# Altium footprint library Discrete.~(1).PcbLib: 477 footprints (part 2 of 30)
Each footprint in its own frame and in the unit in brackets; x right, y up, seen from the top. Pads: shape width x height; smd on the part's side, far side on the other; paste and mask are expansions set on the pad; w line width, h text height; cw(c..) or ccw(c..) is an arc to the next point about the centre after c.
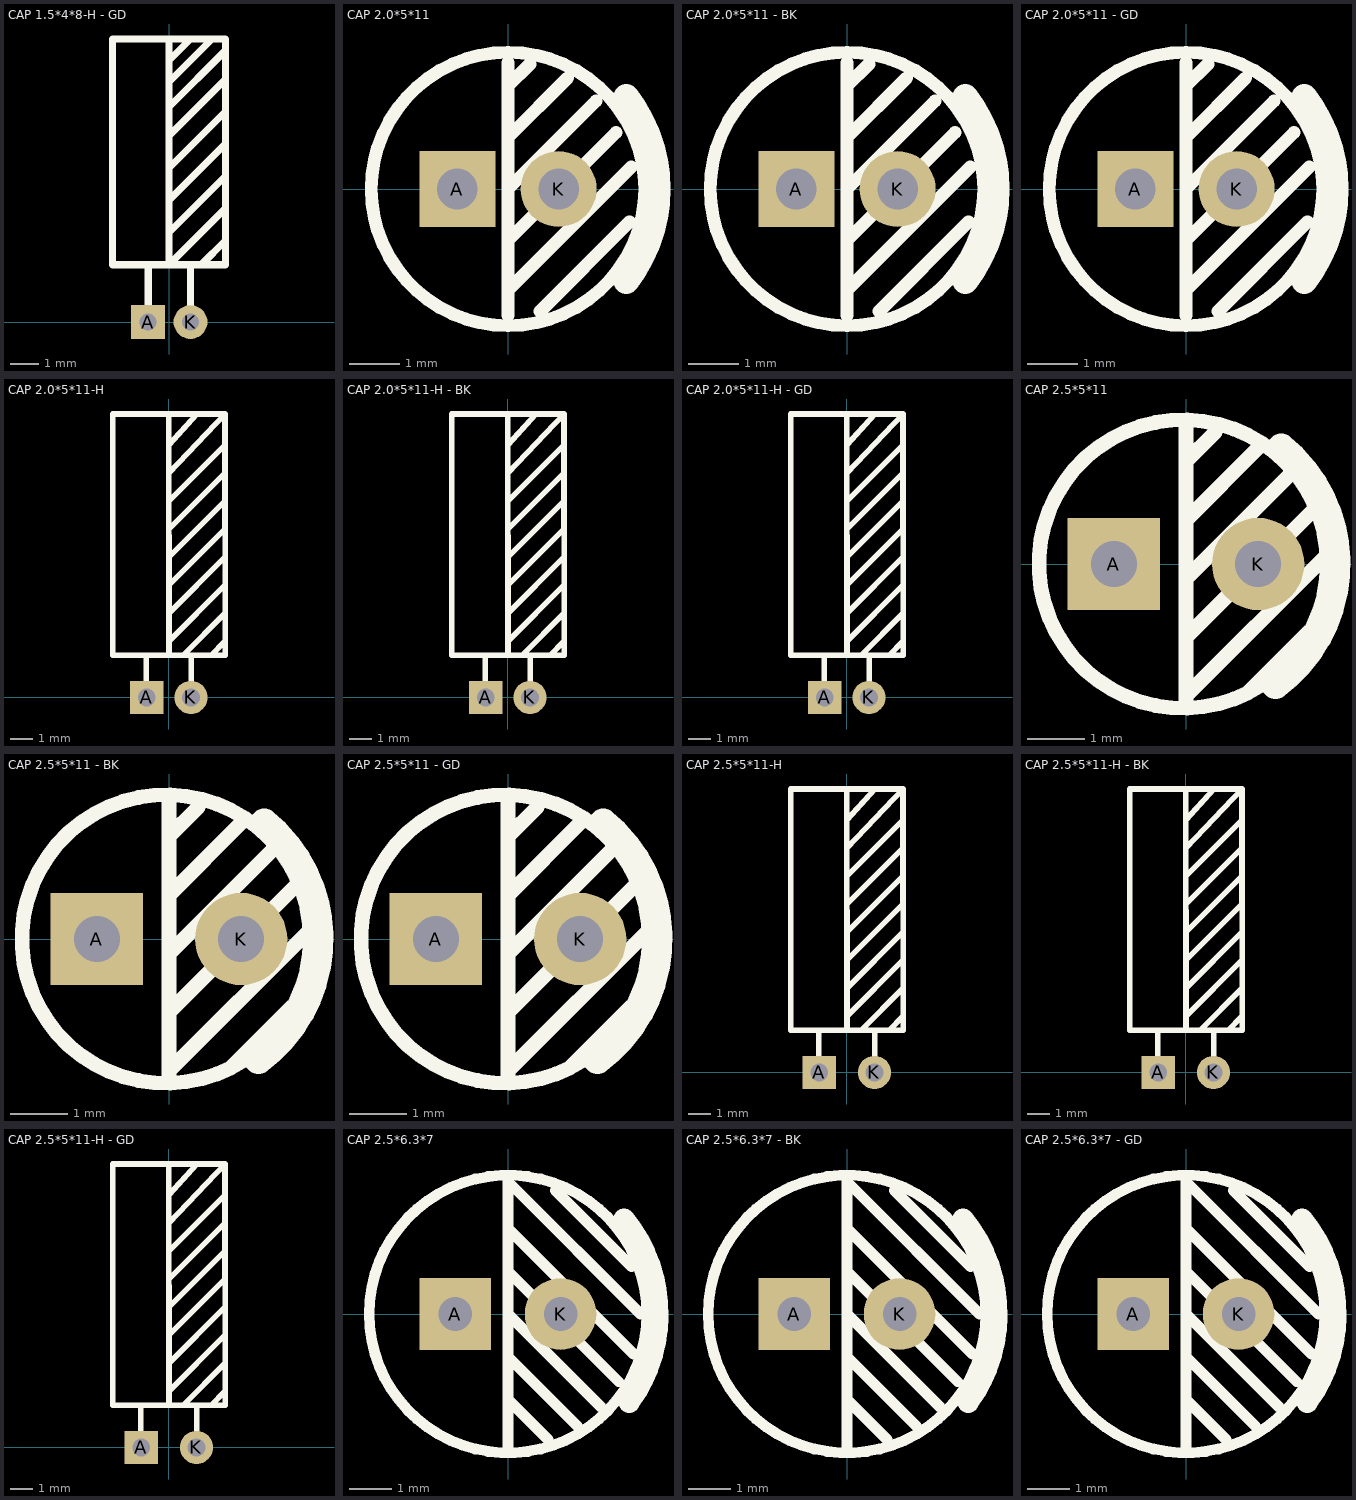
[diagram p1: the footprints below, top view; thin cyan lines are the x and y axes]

## CAP 1.5*4*8-H - GD [mm] "脚距1.5mm直径4mm高度8mm"
pads (2):
  rect 1.2x1.2 hole 0.6: A(-0.75,0)
  round 1.2 hole 0.6: K(0.75,0)
Top Overlay:
  lines w0.254: -0.75,0 -0.75,2 ; -0.012,3.175 1.988,5.175 1.988,5.207 ; -0.012,4.318 1.988,6.318 1.988,6.35 ; -0.012,5.461 1.988,7.461 1.988,7.493 ; -0.012,6.604 1.988,8.604 1.988,8.636 ; -0.012,7.62 1.965,9.597 ccw(c1.911,9.652) 1.988,9.652 ; -0.012,8.509 1.51,10.031 cw(c1.512,10.03) 1.512,10.032 ; -0.012,9.271 0.748,10.031 cw(c0.75,10.03) 0.75,10.032 ; -0.012,10.032 -0.012,2.032 ; 0.75,0 0.75,2 ; 0.877,2.921 -0.012,2.032 ; 1.131,2.032 1.988,2.889 1.988,2.921 ; 1.988,4.064 1.988,4.032 -0.012,2.032 ; -2.012,2.032 1.988,2.032 1.988,10.032 -2.012,10.032 -2.012,2.032
3D body "CAP 1.5X4X8-H.STEP": height 4.02, standoff -3.48, extent -2,-0.25 2.02,10

## CAP 2.0*5*11 [mm] "脚距2mm直径5mm高度11mm"
pads (2):
  rect 1.5x1.5 hole 0.8: A(-1,0)
  round 1.5 hole 0.8: K(1,0)
Top Overlay:
  circle w0.254: c0,0 r2.7
  lines w0.254: 0,-2.5 0,-2 ; 0,-1.016 2.134,1.118 ; 0,0 1.74,1.74 ; 0,1.016 1.181,2.197 ; 0,2.032 0.432,2.464 ; 0,2.5 0,-2 ; 0.635,-2.413 2.4,-0.648 ; 2.435,0.435 0,-2
  lines w0.5: 2.338,-1.819 ccw(c0,0) 2.338,1.819
3D body "CAP 2X5X11.STEP": height 11.04, standoff -3.42, extent -2.5,-2.499 2.51,2.499

## CAP 2.0*5*11 - BK [mm] "脚距2mm直径5mm高度11mm"
pads (2):
  rect 1.5x1.5 hole 0.8: A(-1,0)
  round 1.5 hole 0.8: K(1,0)
Top Overlay:
  circle w0.254: c0,0 r2.7
  lines w0.254: 0,-2.5 0,-2 ; 0,-1.016 2.134,1.118 ; 0,0 1.74,1.74 ; 0,1.016 1.181,2.197 ; 0,2.032 0.432,2.464 ; 0,2.5 0,-2 ; 0.635,-2.413 2.4,-0.648 ; 2.435,0.435 0,-2
  lines w0.5: 2.338,-1.819 ccw(c0,0) 2.338,1.819
3D body "CAP 2X5X11.STEP": height 11.04, standoff -3.42, extent -2.5,-2.499 2.51,2.499

## CAP 2.0*5*11 - GD [mm] "脚距2mm直径5mm高度11mm"
pads (2):
  rect 1.5x1.5 hole 0.8: A(-1,0)
  round 1.5 hole 0.8: K(1,0)
Top Overlay:
  circle w0.254: c0,0 r2.7
  lines w0.254: 0,-2.5 0,-2 ; 0,-1.016 2.134,1.118 ; 0,0 1.74,1.74 ; 0,1.016 1.181,2.197 ; 0,2.032 0.432,2.464 ; 0,2.5 0,-2 ; 0.635,-2.413 2.4,-0.648 ; 2.435,0.435 0,-2
  lines w0.5: 2.338,-1.819 ccw(c0,0) 2.338,1.819
3D body "CAP 2X5X11.STEP": height 11.04, standoff -3.42, extent -2.5,-2.499 2.51,2.499

## CAP 2.0*5*11-H [mm] "脚距2mm直径5mm高度11mm"
pads (2):
  rect 1.5x1.5 hole 0.8: A(-1,0)
  round 1.5 hole 0.8: K(1,0)
Top Overlay:
  lines w0.254: -1.016,0.762 -1.016,1.905 ; 0,2.54 2.548,5.08 ; 0,6.35 2.54,8.89 ; 0.001,11.43 1.27,12.827 ; 0,12.827 0.006,1.905 ; 0.001,10.16 2.54,12.827 ; 0.003,7.62 2.543,10.16 ; 0.002,8.89 2.541,11.43 ; 0.004,5.08 2.545,7.62 ; 0.005,3.81 2.547,6.35 ; 0.635,1.905 2.54,3.81 ; 1.016,0.762 1.016,1.905 ; 1.905,1.905 2.54,2.54 ; 2.54,12.827 2.552,1.905 -2.54,1.905 -2.54,12.827 2.54,12.827
3D body "CAP 2X5X11-H.STEP": height 5.02, standoff -3.48, extent -2.5,-0.25 2.51,12.96

## CAP 2.0*5*11-H - BK [mm] "脚距2mm直径5mm高度11mm"
pads (2):
  rect 1.5x1.5 hole 0.8: A(-1,0)
  round 1.5 hole 0.8: K(1,0)
Top Overlay:
  lines w0.254: -1.016,0.762 -1.016,1.905 ; 0,2.54 2.548,5.08 ; 0,6.35 2.54,8.89 ; 0.001,11.43 1.27,12.827 ; 0,12.827 0.006,1.905 ; 0.001,10.16 2.54,12.827 ; 0.003,7.62 2.543,10.16 ; 0.002,8.89 2.541,11.43 ; 0.004,5.08 2.545,7.62 ; 0.005,3.81 2.547,6.35 ; 0.635,1.905 2.54,3.81 ; 1.016,0.762 1.016,1.905 ; 1.905,1.905 2.54,2.54 ; 2.54,12.827 2.552,1.905 -2.54,1.905 -2.54,12.827 2.54,12.827
3D body "CAP 2X5X11-H.STEP": height 5.02, standoff -3.48, extent -2.5,-0.25 2.51,12.96

## CAP 2.0*5*11-H - GD [mm] "脚距2mm直径5mm高度11mm"
pads (2):
  rect 1.5x1.5 hole 0.8: A(-1,0)
  round 1.5 hole 0.8: K(1,0)
Top Overlay:
  lines w0.254: -1.016,0.762 -1.016,1.905 ; 0,2.54 2.548,5.08 ; 0,6.35 2.54,8.89 ; 0.001,11.43 1.27,12.827 ; 0,12.827 0.006,1.905 ; 0.001,10.16 2.54,12.827 ; 0.003,7.62 2.543,10.16 ; 0.002,8.89 2.541,11.43 ; 0.004,5.08 2.545,7.62 ; 0.005,3.81 2.547,6.35 ; 0.635,1.905 2.54,3.81 ; 1.016,0.762 1.016,1.905 ; 1.905,1.905 2.54,2.54 ; 2.54,12.827 2.552,1.905 -2.54,1.905 -2.54,12.827 2.54,12.827
3D body "CAP 2X5X11-H.STEP": height 5.02, standoff -3.48, extent -2.5,-0.25 2.51,12.96

## CAP 2.5*5*11 [mm] "脚距2.5mm直径5mm高度11mm"
pads (2):
  rect 1.6x1.6 hole 0.8: A(-1.25,0)
  round 1.6 hole 0.8: K(1.25,0)
Top Overlay:
  circle w0.254: c-0.05,0 r2.5
  lines w0.254: 0,-2.489 0,2.413 ; 0,-2.286 2.438,0.152 ; 0,-1.27 2.222,0.953 ; 0,-0.254 1.841,1.587 ; 0,0.762 1.27,2.032 ; 0,1.778 0.508,2.286 ; 1.079,-2.222 2.134,-1.168
  lines w0.5: 1.552,-2.086 ccw(c0,0) 1.651,2.008
3D body "CAP 2.5X5X11.STEP": height 11.03, standoff -3.43, extent -2.5,-2.499 2.51,2.499

## CAP 2.5*5*11 - BK [mm] "脚距2.5mm直径5mm高度11mm"
pads (2):
  rect 1.6x1.6 hole 0.8: A(-1.25,0)
  round 1.6 hole 0.8: K(1.25,0)
Top Overlay:
  circle w0.254: c-0.05,0 r2.5
  lines w0.254: 0,-2.489 0,2.413 ; 0,-2.286 2.438,0.152 ; 0,-1.27 2.222,0.953 ; 0,-0.254 1.841,1.587 ; 0,0.762 1.27,2.032 ; 0,1.778 0.508,2.286 ; 1.079,-2.222 2.134,-1.168
  lines w0.5: 1.552,-2.086 ccw(c0,0) 1.651,2.008
3D body "CAP 2.5X5X11.STEP": height 11.04, standoff -3.42, extent -2.5,-2.499 2.51,2.499

## CAP 2.5*5*11 - GD [mm] "脚距2.5mm直径5mm高度11mm"
pads (2):
  rect 1.6x1.6 hole 0.8: A(-1.25,0)
  round 1.6 hole 0.8: K(1.25,0)
Top Overlay:
  circle w0.254: c-0.05,0 r2.5
  lines w0.254: 0,-2.489 0,2.413 ; 0,-2.286 2.438,0.152 ; 0,-1.27 2.222,0.953 ; 0,-0.254 1.841,1.587 ; 0,0.762 1.27,2.032 ; 0,1.778 0.508,2.286 ; 1.079,-2.222 2.134,-1.168
  lines w0.5: 1.552,-2.086 ccw(c0,0) 1.651,2.008
3D body "CAP 2.5X5X11.STEP": height 11.04, standoff -3.42, extent -2.5,-2.537 2.51,2.461

## CAP 2.5*5*11-H [mm] "脚距2.5mm直径5mm高度11mm"
pads (2):
  rect 1.5x1.5 hole 0.8: A(-1.25,0)
  round 1.5 hole 0.8: K(1.25,0)
Top Overlay:
  lines w0.254: -1.266,0.762 -1.266,1.905 ; 0,2.54 2.548,5.08 ; 0,6.35 2.54,8.89 ; 0.001,11.43 1.27,12.827 ; 0,12.827 0.006,1.905 ; 0.001,10.16 2.54,12.827 ; 0.003,7.62 2.543,10.16 ; 0.002,8.89 2.541,11.43 ; 0.004,5.08 2.545,7.62 ; 0.005,3.81 2.547,6.35 ; 0.635,1.905 2.54,3.81 ; 1.266,0.762 1.266,1.905 ; 1.905,1.905 2.54,2.54 ; 2.54,12.827 -2.54,12.827 -2.54,1.905 2.552,1.905 2.54,12.827
3D body "CAP 2.5X5X11-H.STEP": height 5.02, standoff -3.48, extent -2.5,-0.25 2.51,12.96

## CAP 2.5*5*11-H - BK [mm] "脚距2.5mm直径5mm高度11mm"
pads (2):
  rect 1.5x1.5 hole 0.8: A(-1.25,0)
  round 1.5 hole 0.8: K(1.25,0)
Top Overlay:
  lines w0.254: -1.266,0.762 -1.266,1.905 ; 0,2.54 2.548,5.08 ; 0,6.35 2.54,8.89 ; 0.001,11.43 1.27,12.827 ; 0,12.827 0.006,1.905 ; 0.001,10.16 2.54,12.827 ; 0.003,7.62 2.543,10.16 ; 0.002,8.89 2.541,11.43 ; 0.004,5.08 2.545,7.62 ; 0.005,3.81 2.547,6.35 ; 0.635,1.905 2.54,3.81 ; 1.266,0.762 1.266,1.905 ; 1.905,1.905 2.54,2.54 ; 2.54,12.827 2.552,1.905 -2.54,1.905 -2.54,12.827 2.54,12.827
3D body "CAP 2.5X5X11-H.STEP": height 5.02, standoff -3.48, extent -2.5,-0.25 2.51,12.96

## CAP 2.5*5*11-H - GD [mm] "脚距2.5mm直径5mm高度11mm"
pads (2):
  rect 1.5x1.5 hole 0.8: A(-1.25,0)
  round 1.5 hole 0.8: K(1.25,0)
Top Overlay:
  lines w0.254: -1.266,0.762 -1.266,1.905 ; 0,2.54 2.548,5.08 ; 0,6.35 2.54,8.89 ; 0.001,11.43 1.27,12.827 ; 0,12.827 0.006,1.905 ; 0.001,10.16 2.54,12.827 ; 0.003,7.62 2.543,10.16 ; 0.002,8.89 2.541,11.43 ; 0.004,5.08 2.545,7.62 ; 0.005,3.81 2.547,6.35 ; 0.635,1.905 2.54,3.81 ; 1.266,0.762 1.266,1.905 ; 1.905,1.905 2.54,2.54 ; 2.54,12.827 2.552,1.905 -2.54,1.905 -2.54,12.827 2.54,12.827
3D body "CAP 2.5X5X11-H.STEP": height 5.02, standoff -3.48, extent -2.5,-0.25 2.51,12.96

## CAP 2.5*6.3*7 [mm] "脚距2.5mm直径6.3mm高度7mm"
pads (2):
  rect 1.7x1.7 hole 0.8: A(-1.25,0)
  round 1.7 hole 0.8: K(1.25,0)
Top Overlay:
  circle w0.254: c0,0 r3.3
  lines w0.254: 0,-3.15 0,3.15 ; 0,-2.032 0.953,-2.984 ; 0,-1.016 1.638,-2.654 ; 0,0 2.21,-2.21 ; 0,1.016 2.629,-1.613 ; 0,2.032 2.984,-0.953 ; 0,3.048 0.102,3.048 3.15,0 ; 1.13,2.934 2.934,1.13
  lines w0.504: 2.759,2.258 cw(c0,0) 2.883,-2.097
3D body "CAP 2.5X6.3X7.STEP": height 7.03, standoff -3.38, extent -3.15,-3.15 3.16,3.15

## CAP 2.5*6.3*7 - BK [mm] "脚距2.5mm直径6.3mm高度7mm"
pads (2):
  rect 1.7x1.7 hole 0.8: A(-1.25,0)
  round 1.7 hole 0.8: K(1.25,0)
Top Overlay:
  circle w0.254: c0,0 r3.3
  lines w0.254: 0,-3.15 0,3.15 ; 0,-2.032 0.953,-2.984 ; 0,-1.016 1.638,-2.654 ; 0,0 2.21,-2.21 ; 0,1.016 2.629,-1.613 ; 0,2.032 2.984,-0.953 ; 0,3.048 0.102,3.048 3.15,0 ; 1.13,2.934 2.934,1.13
  lines w0.504: 2.759,2.258 cw(c0,0) 2.883,-2.097
3D body "CAP 2.5X6.3X7.STEP": height 7.04, standoff -3.37, extent -3.15,-3.15 3.16,3.15

## CAP 2.5*6.3*7 - GD [mm] "脚距2.5mm直径6.3mm高度7mm"
pads (2):
  rect 1.7x1.7 hole 0.8: A(-1.25,0)
  round 1.7 hole 0.8: K(1.25,0)
Top Overlay:
  circle w0.254: c0,0 r3.3
  lines w0.254: 0,-3.15 0,3.15 ; 0,-2.032 0.953,-2.984 ; 0,-1.016 1.638,-2.654 ; 0,0 2.21,-2.21 ; 0,1.016 2.629,-1.613 ; 0,2.032 2.984,-0.953 ; 0,3.048 0.102,3.048 3.15,0 ; 1.13,2.934 2.934,1.13
  lines w0.504: 2.759,2.258 cw(c0,0) 2.883,-2.097
3D body "CAP 2.5X6.3X7.STEP": height 7.04, standoff -3.37, extent -3.15,-3.15 3.16,3.15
